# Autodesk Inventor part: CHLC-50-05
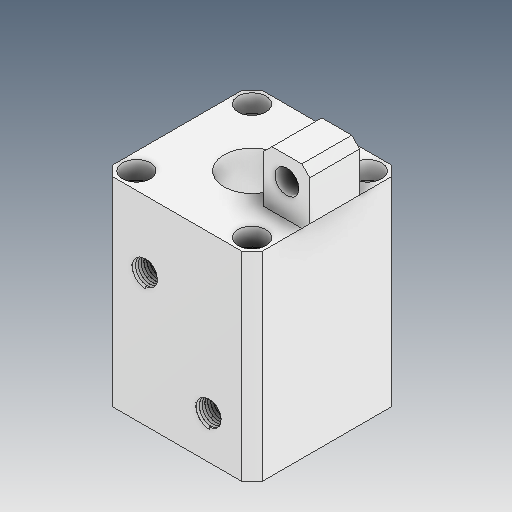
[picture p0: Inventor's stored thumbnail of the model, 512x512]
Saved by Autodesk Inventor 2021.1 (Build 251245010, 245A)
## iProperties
Created: 2021-05
Part Number: CHLC-50-05
Material: Ogólny
Document SubType Name: Modeling
Designer: user
Density: 1 g/cm^3
Appearance: Domyślna
Author: user
Revision Number: ÈÎºÎ
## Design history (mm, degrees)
feature "ÊäÈë1"
node "Bryła1"
